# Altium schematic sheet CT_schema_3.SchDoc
size 302 x 256 mm
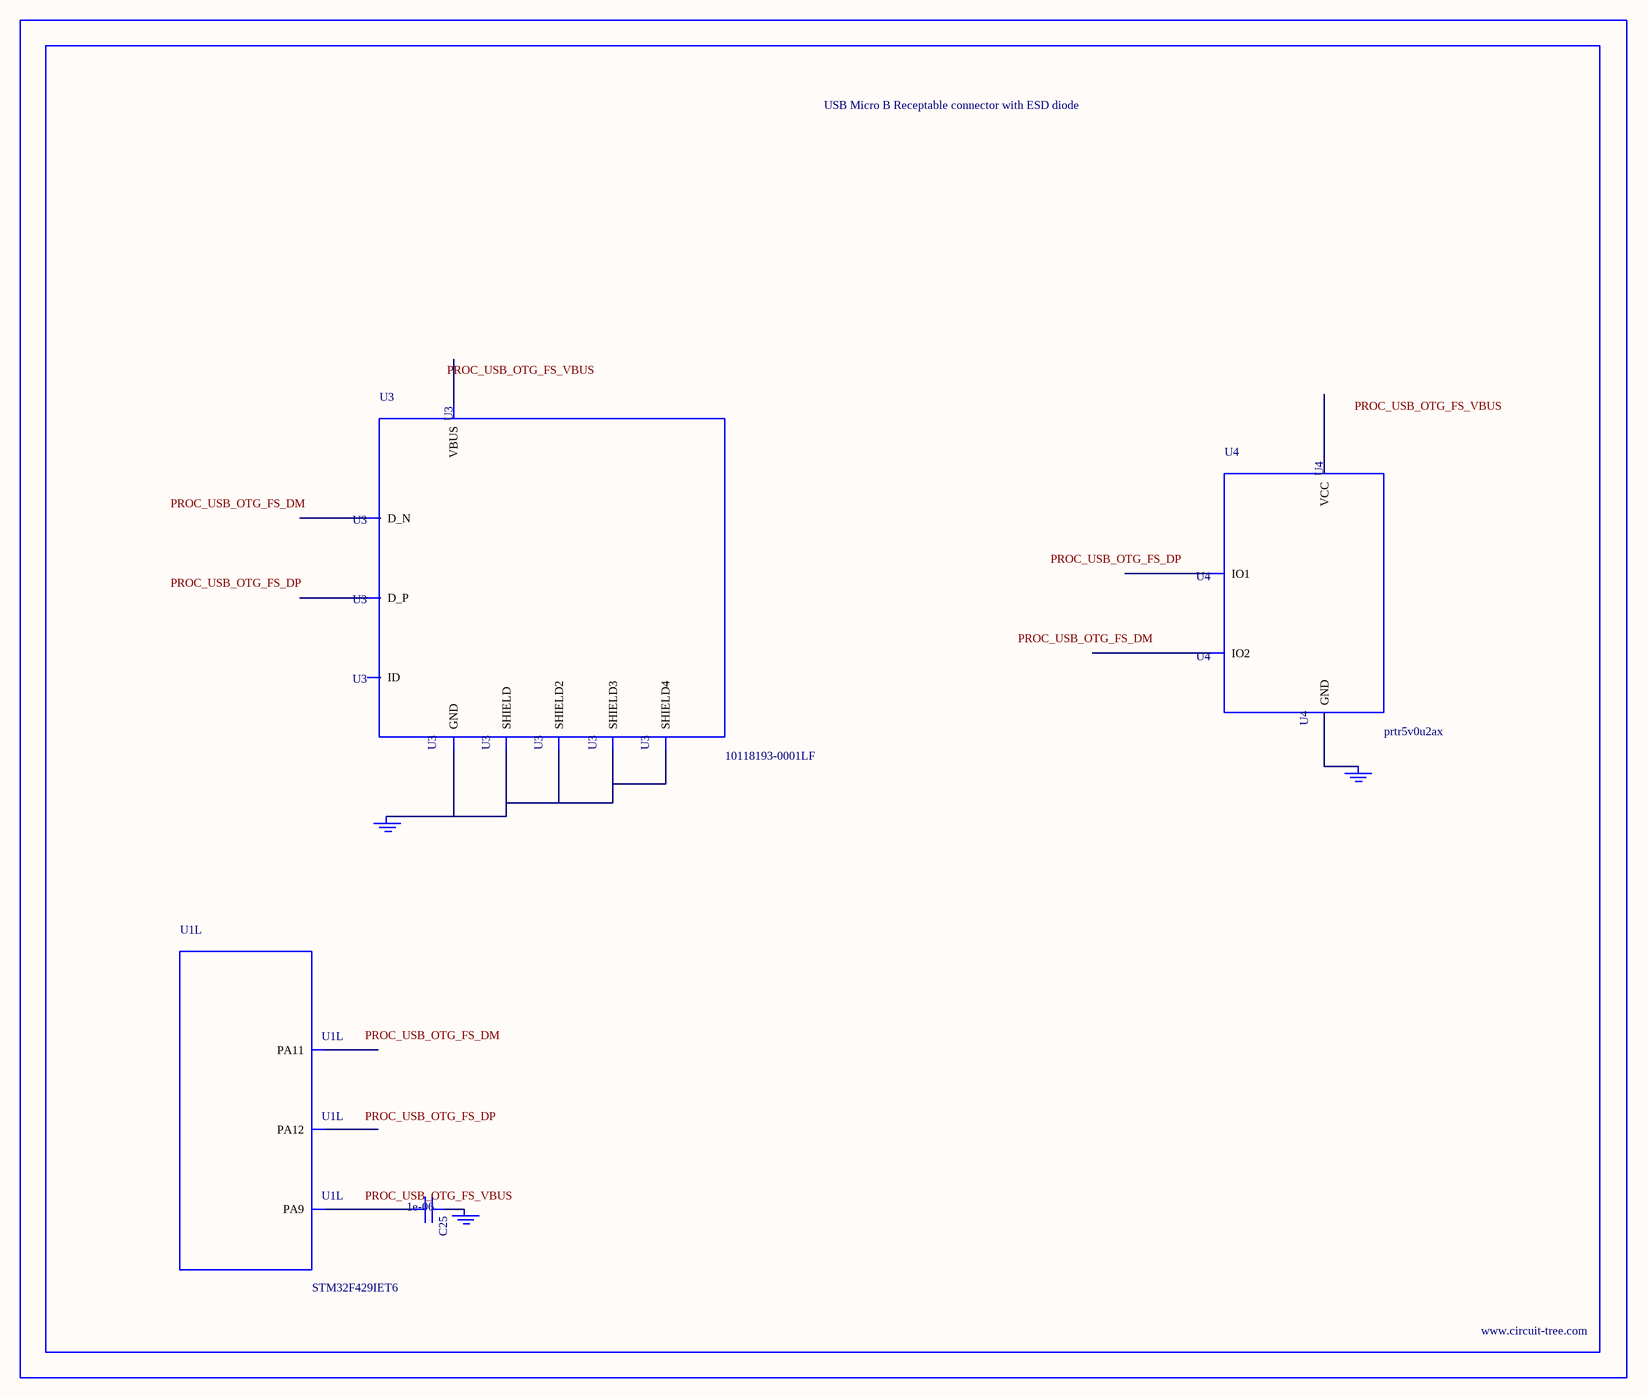
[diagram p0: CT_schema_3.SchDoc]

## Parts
BORDER2  (no value)
C25  1e-06  [C0603]
GND_INSTANCE_2_0  (no value)
GND_INSTANCE_2_1  (no value)
GND_INSTANCE_2_2  (no value)
U1  STM32F429IET6  [LQFP176]  (part L of 13)
U3  10118193-0001LF  [FCI_10118193-0001LF]
U4  prtr5v0u2ax  [SOT143B]

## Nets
NetC25_1: C25.1 GND_INSTANCE_2_1.0(GND)
NetC25_2: C25.2 U1.120(PA9)
NetGND_INSTANCE_2_0_0: GND_INSTANCE_2_0.0(GND) U3.5(GND) U3.6(SHIELD) U3.7(SHIELD2) U3.8(SHIELD3) U3.9(SHIELD4)
NetGND_INSTANCE_2_2_0: GND_INSTANCE_2_2.0(GND) U4.1(GND)

Not connected (* = marked no-connect by the designer): U1 122(PA11) 123(PA12); U3 1(VBUS) 2(D_N) 3(D_P) 4(ID); U4 2(IO1) 3(IO2) 4(VCC)

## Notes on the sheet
- Labels drawn without touching a wire or pin: PROC_USB_OTG_FS_DM, PROC_USB_OTG_FS_DP, PROC_USB_OTG_FS_VBUS

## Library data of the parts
BORDER2 = BORDER_PAGE2
C25 = C0603C105K3RACTU
GND_INSTANCE_2_0-GND_INSTANCE_2_2 = GND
